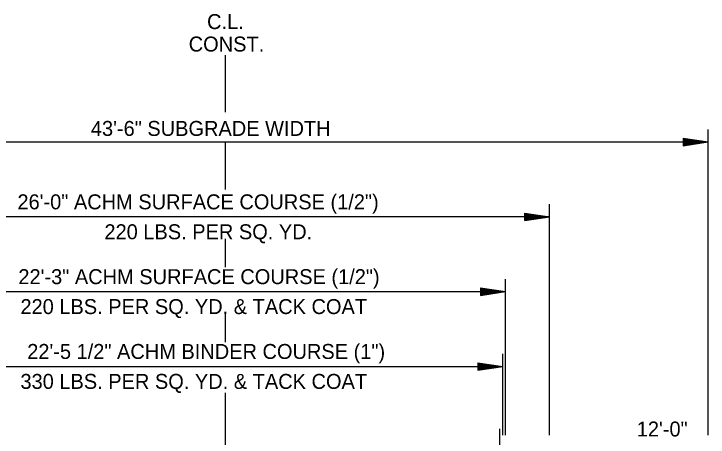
# Model space of a CAD drawing. Extents: x 138 to 3619, y -519 to 1449.
# Drawn here: x 526.3 to 804.9, y 607.1 to 776.7 of the extents above; entities that cross this region are included whole.
import ezdxf

# ---------------------------------------------------------------- set-up
doc = ezdxf.new("R2010")
doc.units = 0
for name, color, linetype in [('R_Annotation', 7, 'Continuous'), ('R_Centerline', 7, 'Continuous'), ('R_Dimension', 7, 'Continuous')]:
    doc.layers.add(name, color=color, linetype=linetype)

msp = doc.modelspace()

# ---------------------------------------------------------------- linework, layer by layer
at = {"layer": 'R_Centerline'}
for p, q in [((611.26, 737.35), (611.26, 760.16)), ((611.26, 706.28), (611.26, 725.39)), ((611.26, 675.17), (611.26, 686.59)), ((611.26, 645.17), (611.26, 656.59)), ((611.26, 546.06), (611.26, 624.77))]:
    msp.add_line(p, q, dxfattribs=at)
at = {"layer": 'R_Dimension'}
for p, q in [((804.9, 607.89), (804.9, 730.39)), ((417.63, 725.39), (804.9, 725.39)), ((794.9, 726.89), (804.9, 725.39)), ((794.9, 726.89), (794.9, 723.89)), ((794.9, 726.64), (803.23, 725.39)), ((794.9, 726.39), (801.51, 725.39)), ((794.9, 726.14), (799.84, 725.39)), ((794.9, 725.88), (798.15, 725.39)), ((794.9, 725.63), (796.48, 725.39)), ((794.9, 723.89), (804.9, 725.39)), ((794.9, 724.9), (798.15, 725.39)), ((794.9, 724.4), (801.51, 725.39)), ((794.9, 724.14), (803.23, 725.39)), ((794.9, 724.65), (799.84, 725.39)), ((794.9, 725.16), (796.48, 725.39)), ((741.28, 607.89), (741.28, 700.39)), ((731.28, 696.89), (741.28, 695.39)), ((731.28, 693.89), (731.28, 696.89)), ((731.28, 696.64), (739.61, 695.39)), ((741.28, 695.39), (481.25, 695.39)), ((731.28, 696.39), (737.89, 695.39)), ((731.28, 696.14), (736.22, 695.39)), ((731.28, 695.88), (734.53, 695.39)), ((731.28, 695.63), (732.86, 695.39)), ((731.28, 693.89), (741.28, 695.39)), ((731.28, 694.91), (734.53, 695.39)), ((731.28, 694.4), (737.89, 695.39)), ((731.28, 694.14), (739.61, 695.39)), ((731.28, 694.65), (736.22, 695.39)), ((731.28, 695.16), (732.86, 695.39)), ((723.58, 607.89), (723.58, 670.39)), ((713.58, 666.89), (723.58, 665.39)), ((713.58, 666.89), (713.58, 663.89)), ((713.58, 666.64), (721.91, 665.39)), ((713.58, 666.39), (720.19, 665.39)), ((713.58, 666.14), (718.53, 665.39)), ((500, 665.39), (722.53, 665.39)), ((713.58, 665.88), (716.83, 665.39)), ((713.58, 665.63), (715.16, 665.39)), ((713.58, 663.89), (723.58, 665.39)), ((713.58, 664.9), (716.83, 665.39)), ((713.58, 664.4), (720.19, 665.39)), ((713.58, 664.14), (721.91, 665.39)), ((713.58, 664.65), (718.53, 665.39)), ((713.58, 665.16), (715.16, 665.39)), ((722.53, 607.89), (722.53, 640.39)), ((500, 635.39), (722.53, 635.39)), ((712.53, 636.89), (722.53, 635.39)), ((712.53, 636.89), (712.53, 633.89)), ((712.53, 636.64), (720.86, 635.39)), ((712.53, 636.39), (719.14, 635.39)), ((712.53, 636.14), (717.48, 635.39)), ((712.53, 635.88), (715.78, 635.39)), ((712.53, 635.63), (714.11, 635.39)), ((712.53, 633.89), (722.53, 635.39)), ((712.53, 634.9), (715.78, 635.39)), ((712.53, 634.4), (719.14, 635.39)), ((712.53, 634.14), (720.86, 635.39)), ((712.53, 634.65), (717.48, 635.39)), ((712.53, 635.16), (714.11, 635.39)), ((721.26, 585.39), (721.26, 610.39))]:
    msp.add_line(p, q, dxfattribs=at)

# ---------------------------------------------------------------- texts
at = {"layer": 'R_Annotation'}
for s, p in [('C.L.', (603.8, 770.66)), ('CONST.', (596.43, 761.66)), ('43\'-6" SUBGRADE WIDTH', (557.17, 727.82)), ('26\'-0" ACHM SURFACE COURSE (1/2")', (527.69, 698.39)), ('220 LBS. PER SQ. YD.', (562.6, 686.39)), ('22\'-3" ACHM SURFACE COURSE (1/2")', (528.07, 668.39)), ('220 LBS. PER SQ. YD. & TACK COAT', (528.89, 656.39)), ('22\'-5 1/2" ACHM BINDER COURSE (1")', (531.61, 638.39)), ('330 LBS. PER SQ. YD. & TACK COAT', (528.9, 626.39)), ('12\'-0"', (776.26, 607.3))]:
    msp.add_text(s, height=6, dxfattribs=at).set_placement(p)

doc.saveas('drawing.dxf')
